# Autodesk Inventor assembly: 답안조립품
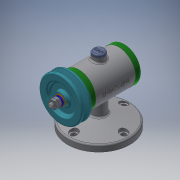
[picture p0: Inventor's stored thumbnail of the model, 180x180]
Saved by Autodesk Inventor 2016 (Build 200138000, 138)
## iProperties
Created: 2018-12
Part Number: 답안조립품
Material: 일반
Document SubType Name: Assembly
Designer: USER
Author: USER
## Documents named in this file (15)
- C:\Users\USER\Desktop\481207V1042\답안조립품.iam
- C:\Users\USER\Desktop\481207V1042\본체.ipt
- C:\Users\USER\Desktop\481207V1042\V벨트풀리.ipt
- C:\Users\USER\Desktop\481207V1042\고무캡.ipt
- C:\Users\USER\Desktop\481207V1042\너트 M8.ipt
- 너트 M8.ipt
- C:\Users\USER\Desktop\481207V1042\뒤커버.ipt
- C:\Users\USER\Desktop\481207V1042\베어링 15 x 32 x 9.ipt
- C:\Users\USER\Desktop\481207V1042\볼트 M4 x 12.ipt
- C:\Users\USER\Desktop\481207V1042\스프링와셔 8.ipt
- C:\Users\USER\Desktop\481207V1042\앞커버.ipt
- C:\Users\USER\Desktop\481207V1042\오일 실 15 25 7.ipt
- C:\Users\USER\Desktop\481207V1042\와셔 8x17.ipt
- C:\Users\USER\Desktop\481207V1042\축.ipt
- C:\Users\USER\Desktop\481207V1042\키 3 x 3 x 12.ipt
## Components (2 placed, 2 different names)
1. V벨트풀리:1
2. 고무캡:1
